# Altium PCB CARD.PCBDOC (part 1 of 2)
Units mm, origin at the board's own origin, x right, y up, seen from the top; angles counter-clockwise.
Board outline 129.79 x 109.73 mm, 2 copper layers (Top Layer, Bottom Layer); 204 components, 30 nets, 765 pads, 348 vias.
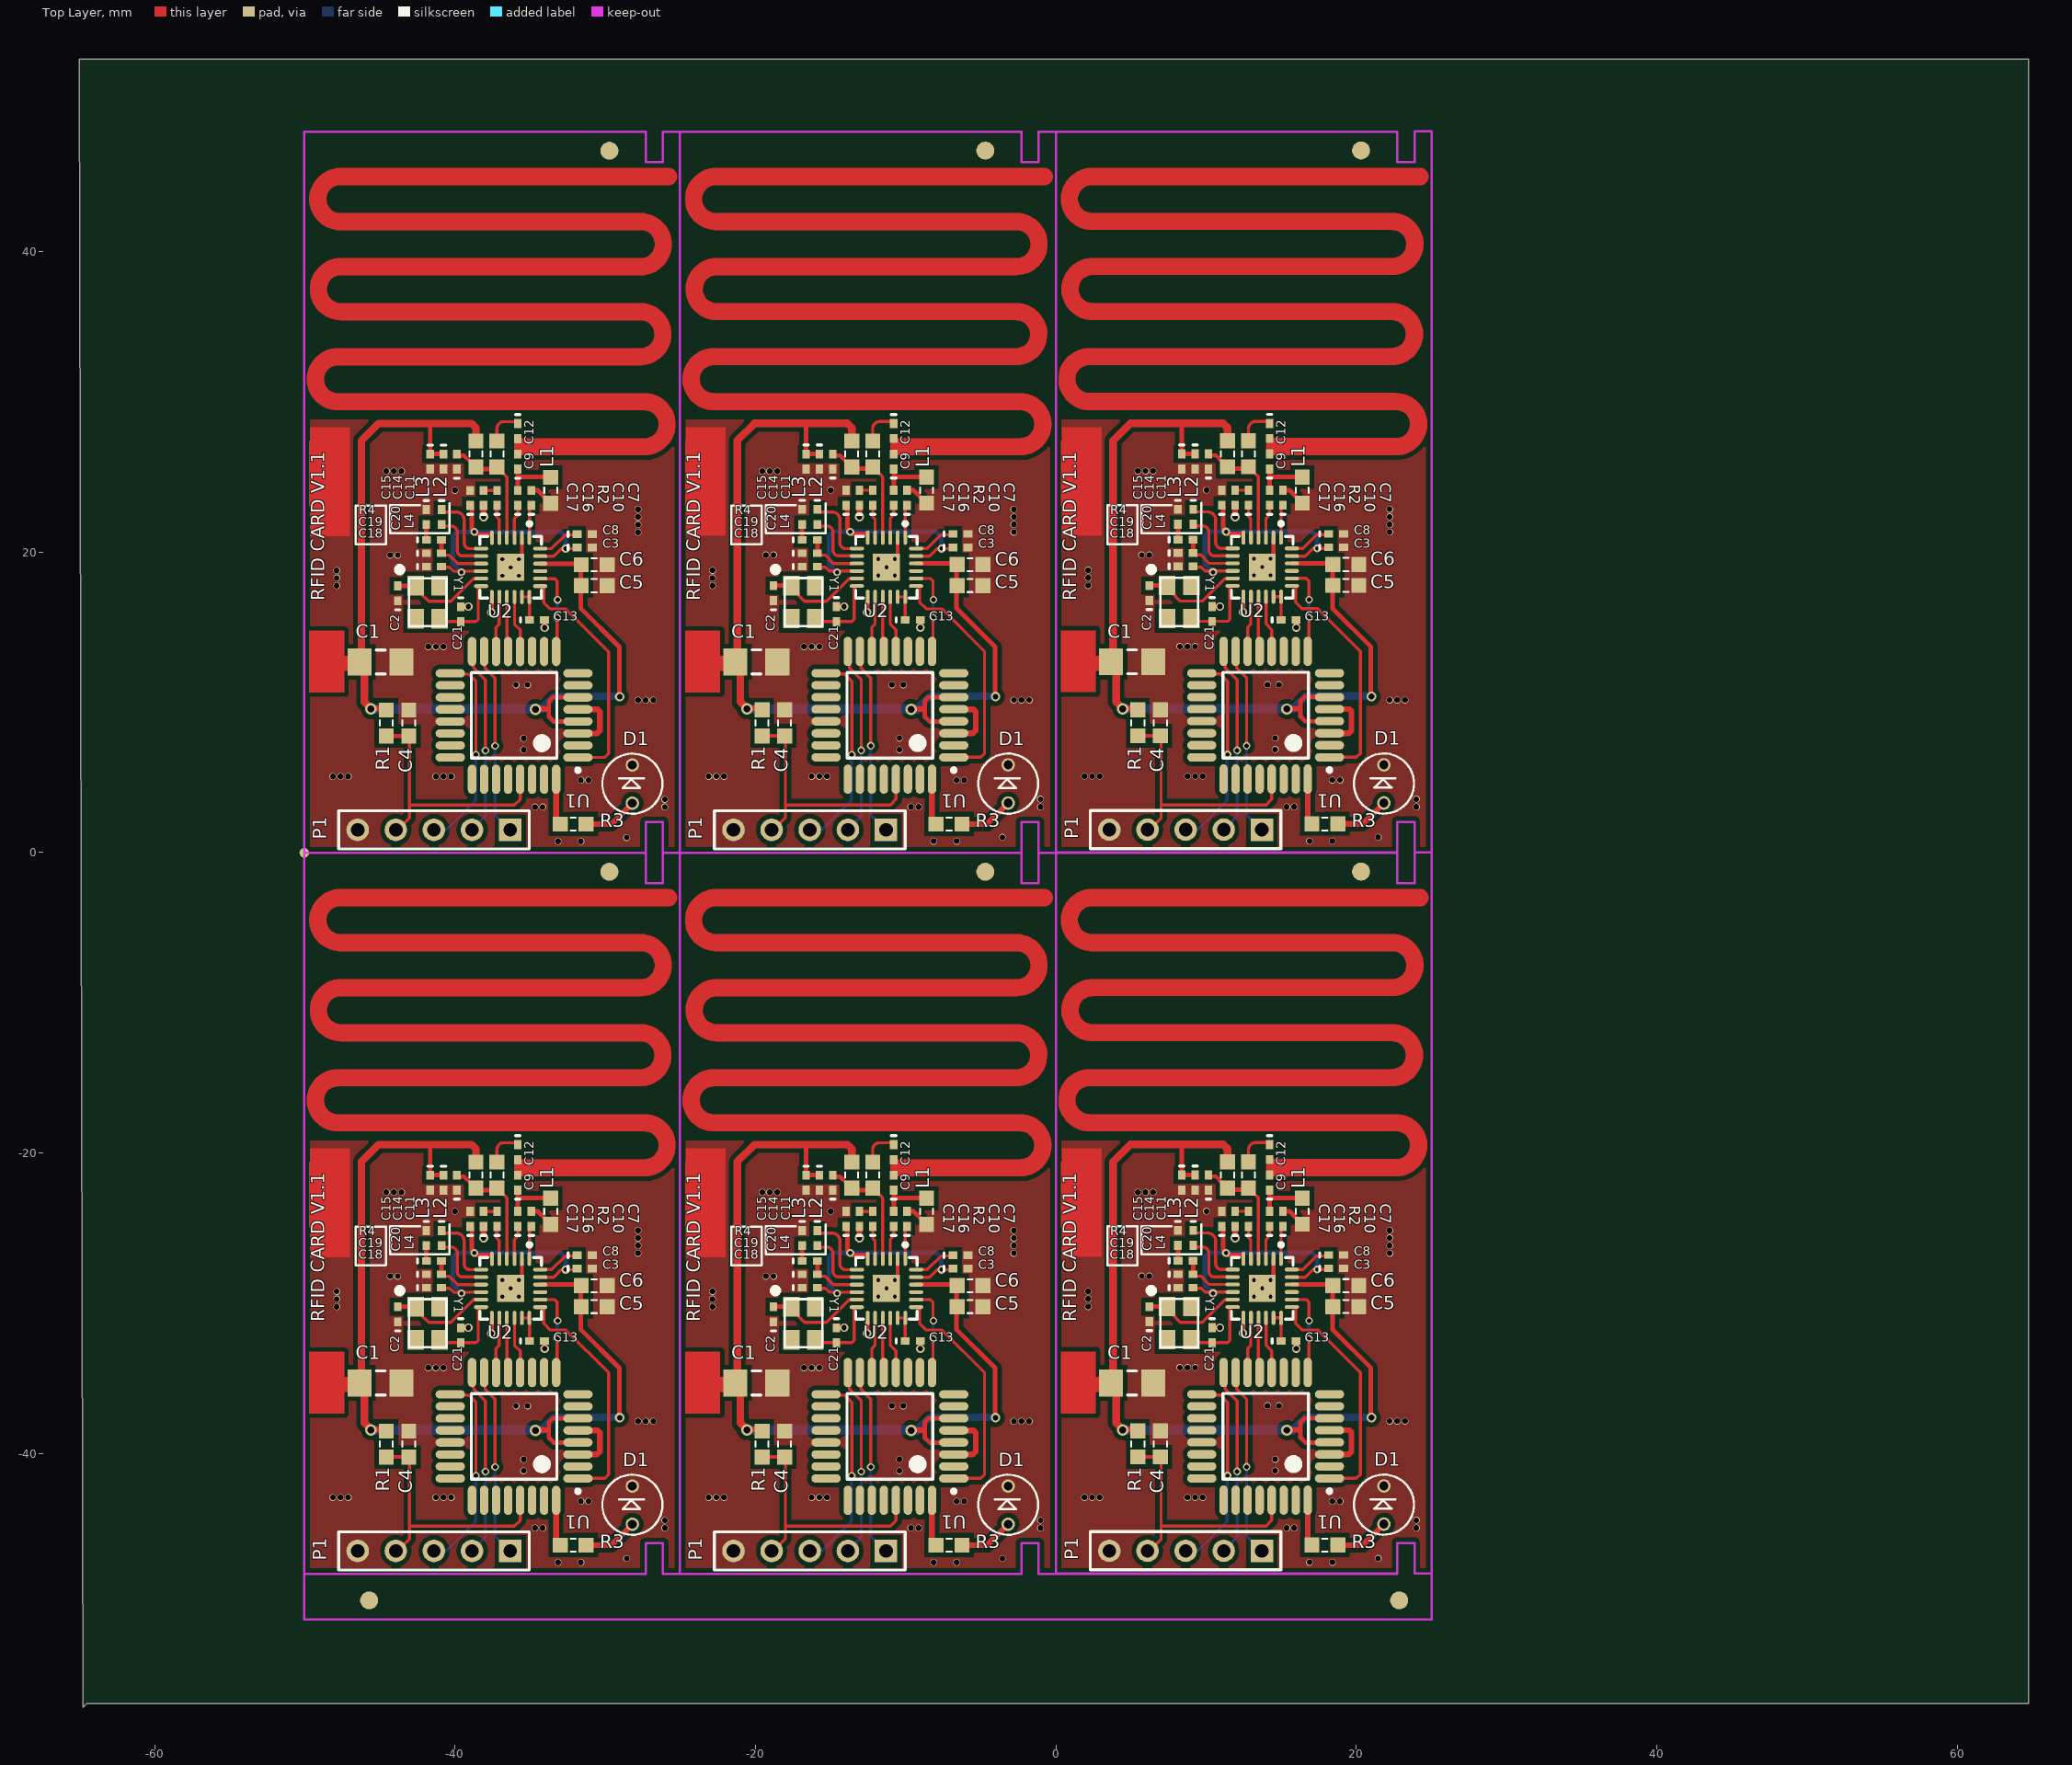
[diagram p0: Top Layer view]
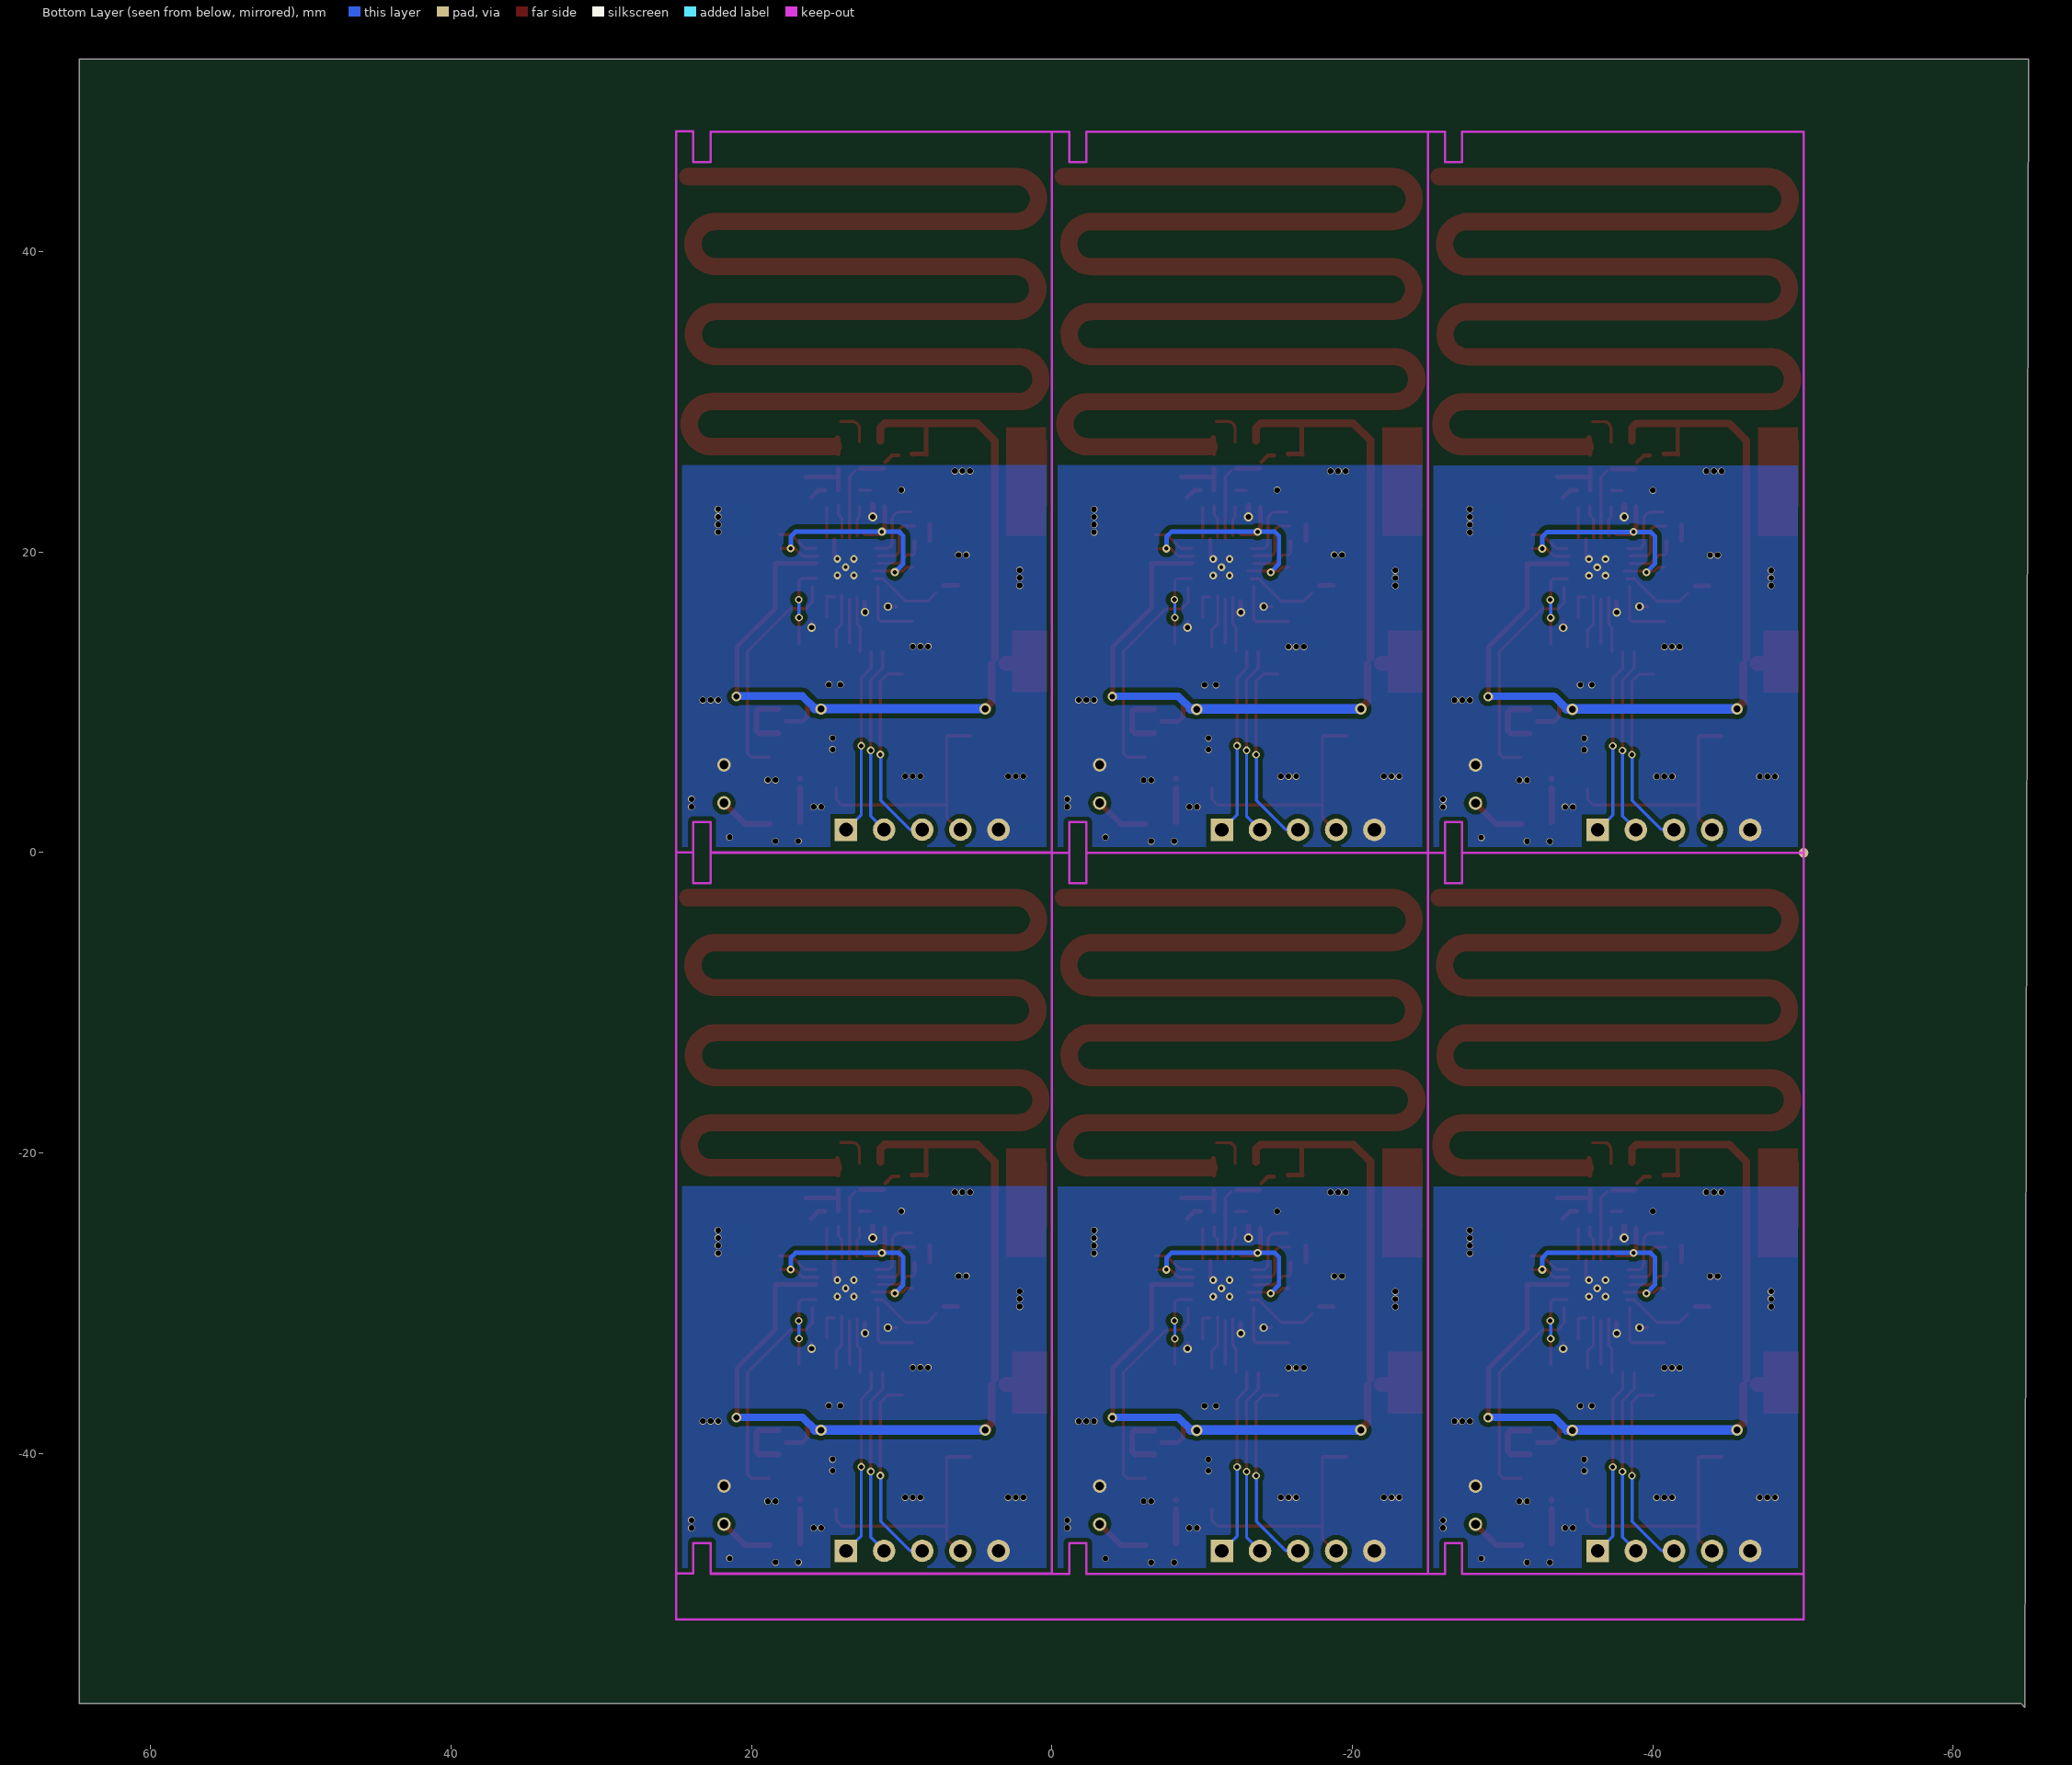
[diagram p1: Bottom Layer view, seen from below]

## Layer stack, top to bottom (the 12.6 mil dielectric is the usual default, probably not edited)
Top Layer: signal copper 0.0356
Dielectric: core 0.32, FR-4, Dk 4.8
Bottom Layer: signal copper 0.0356

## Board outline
-65.024,52.832 64.77,52.832 64.77,-56.642 -64.516,-56.642 -64.77,-56.896

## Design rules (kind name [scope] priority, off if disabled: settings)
Clearance [All] p1 off: gap=0.305
ComponentClearance [All] p1 off: gap=0.254 collisioncheckmode=3 verticalgap=0.254
HoleSize [All] p1: absolutevalues=TRUE maxlimit=2.54 minlimit=0 maxpercent=80.000 minpercent=20.000
PolygonConnect [All] p1: connectstyle=Direct reliefconductorwidth=0.254 reliefentries=4 polygonreliefangle="90 Angle"
RoutingVias [All] p1: holewidth=0.381 width=0.635 viastyle="Through Hole" minholewidth=0.203 minwidth=0.381 maxholewidth=2.032 maxwidth=1.27
SolderMaskExpansion [All] p1: expansion=0.102
TestPointUsage [All] p1: valid=0 allowmultiple=FALSE
Testpoint [All] p1: side=15 testpointundercomponent=TRUE minsize=1.016 maxsize=2.54 preferedsize=1.524 minholesize=0 maxholesize=1.016 preferedholesize=0.813 testpointgrid=0.025 style=1023 order=0123456789
Width [All] p1: maxlimit=2.54 minlimit=0.203 preferedwidth=0.254 minimp=50.000000 maximp=50.000000 favimp=50.000000
17 further rules are at their usual default settings.

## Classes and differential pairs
component class card: C1 C2 C3 C4 C5 C6 C7 C8 C9 C10 C11 C12 C13 C14 C15 C16 C17 C18 C19 C20 C21 D1 D2 L1 L2 L3 L4 P1 P3 R1 R2 R3 R4 U1 U2 Y1

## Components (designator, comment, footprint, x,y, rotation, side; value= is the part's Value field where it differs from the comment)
C1 "Cap" 3216[1206] -44.958,12.688 r180 top
C1 "Cap" 3216[1206] -44.958,-35.312 r180 top
C1 "Cap" 3216[1206] 5.08,-35.306 r180 top
C1 "Cap" 3216[1206] -19.939,-35.312 r180 top
C1 "Cap" 3216[1206] -19.939,12.694 r180 top
C1 "Cap" 3216[1206] 5.08,12.7 r180 top
C2 "Cap" 0402-A -43.815,17.26 r90 top
C2 "Cap" 0402-A -43.815,-30.74 r90 top
C2 "Cap" 0402-A 6.223,-30.734 r90 top
C2 "Cap" 0402-A -18.796,-30.74 r90 top
C2 "Cap" 0402-A -18.796,17.266 r90 top
C2 "Cap" 0402-A 6.223,17.272 r90 top
C3 "Cap" 0402-A -31.369,20.308 r0 top
C3 "Cap" 0402-A -31.369,-27.692 r0 top
C3 "Cap" 0402-A 18.669,-27.686 r0 top
C3 "Cap" 0402-A -6.35,-27.692 r0 top
C3 "Cap" 0402-A -6.35,20.314 r0 top
C3 "Cap" 0402-A 18.669,20.32 r0 top
C4 "Cap" 0603 -43.078,8.624 r90 top
C4 "Cap" 0603 -43.078,-39.376 r90 top
C4 "Cap" 0603 6.96,-39.37 r90 top
C4 "Cap" 0603 -18.059,-39.376 r90 top
C4 "Cap" 0603 -18.059,8.63 r90 top
C4 "Cap" 0603 6.96,8.636 r90 top
C5 "Cap" 0603 -30.734,17.768 r0 top
C5 "Cap" 0603 -30.734,-30.232 r0 top
C5 "Cap" 0603 19.304,-30.226 r0 top
C5 "Cap" 0603 -5.715,-30.232 r0 top
C5 "Cap" 0603 -5.715,17.774 r0 top
C5 "Cap" 0603 19.304,17.78 r0 top
C6 "Cap" 0603 -30.734,19.165 r0 top
C6 "Cap" 0603 -30.734,-28.835 r0 top
C6 "Cap" 0603 19.304,-28.829 r0 top
C6 "Cap" 0603 -5.715,-28.835 r0 top
C6 "Cap" 0603 -5.715,19.171 r0 top
C6 "Cap" 0603 19.304,19.177 r0 top
C7 "Cap" 0402-A -34.925,23.61 r90 top
C7 "Cap" 0402-A -34.925,-24.39 r90 top
C7 "Cap" 0402-A 15.113,-24.384 r90 top
C7 "Cap" 0402-A -9.906,-24.39 r90 top
C7 "Cap" 0402-A -9.906,23.616 r90 top
C7 "Cap" 0402-A 15.113,23.622 r90 top
C8 "Cap" 0402-A -31.369,21.197 r0 top
C8 "Cap" 0402-A -31.369,-26.803 r0 top
C8 "Cap" 0402-A 18.669,-26.797 r0 top
C8 "Cap" 0402-A -6.35,-26.803 r0 top
C8 "Cap" 0402-A -6.35,21.203 r0 top
C8 "Cap" 0402-A 18.669,21.209 r0 top
C9 "Cap" 0402-A -35.814,26.023 r90 top
C9 "Cap" 0402-A -35.814,-21.977 r90 top
C9 "Cap" 0402-A 14.224,-21.971 r90 top
C9 "Cap" 0402-A -10.795,-21.977 r90 top
C9 "Cap" 0402-A -10.795,26.029 r90 top
C9 "Cap" 0402-A 14.224,26.035 r90 top
C10 "Cap" 0402-A -35.814,23.61 r90 top
C10 "Cap" 0402-A -35.814,-24.39 r90 top
C10 "Cap" 0402-A 14.224,-24.384 r90 top
C10 "Cap" 0402-A -10.795,-24.39 r90 top
C10 "Cap" 0402-A -10.795,23.616 r90 top
C10 "Cap" 0402-A 14.224,23.622 r90 top
C11 "Cap" 0402-A -39.878,26.023 r90 top
C11 "Cap" 0402-A -39.878,-21.977 r90 top
C11 "Cap" 0402-A 10.16,-21.971 r90 top
C11 "Cap" 0402-A -14.859,-21.977 r90 top
C11 "Cap" 0402-A -14.859,26.029 r90 top
C11 "Cap" 0402-A 10.16,26.035 r90 top
C12 "Cap" 0402-A -35.814,28.055 r270 top
C12 "Cap" 0402-A -35.814,-19.945 r270 top
C12 "Cap" 0402-A 14.224,-19.939 r270 top
C12 "Cap" 0402-A -10.795,-19.945 r270 top
C12 "Cap" 0402-A -10.795,28.061 r270 top
C12 "Cap" 0402-A 14.224,28.067 r270 top
C13 "Cap" 0402-A -34.544,15.482 r0 top
C13 "Cap" 0402-A -34.544,-32.518 r0 top
C13 "Cap" 0402-A 15.494,-32.512 r0 top
C13 "Cap" 0402-A -9.525,-32.518 r0 top
C13 "Cap" 0402-A -9.525,15.488 r0 top
C13 "Cap" 0402-A 15.494,15.494 r0 top
C14 "Cap" 0402-A -40.767,26.023 r270 top
C14 "Cap" 0402-A -40.767,-21.977 r270 top
C14 "Cap" 0402-A 9.271,-21.971 r270 top
C14 "Cap" 0402-A -15.748,-21.977 r270 top
C14 "Cap" 0402-A -15.748,26.029 r270 top
C14 "Cap" 0402-A 9.271,26.035 r270 top
C15 "Cap" 0402-A -41.656,26.023 r270 top
C15 "Cap" 0402-A -41.656,-21.977 r270 top
C15 "Cap" 0402-A 8.382,-21.971 r270 top
C15 "Cap" 0402-A -16.637,-21.977 r270 top
C15 "Cap" 0402-A -16.637,26.029 r270 top
C15 "Cap" 0402-A 8.382,26.035 r270 top
C16 "Cap" 0402-A -38.1,23.61 r90 top
C16 "Cap" 0402-A -38.1,-24.39 r90 top
C16 "Cap" 0402-A 11.938,-24.384 r90 top
C16 "Cap" 0402-A -13.081,-24.39 r90 top
C16 "Cap" 0402-A -13.081,23.616 r90 top
C16 "Cap" 0402-A 11.938,23.622 r90 top
C17 "Cap" 0402-A -38.989,23.61 r90 top
C17 "Cap" 0402-A -38.989,-24.39 r90 top
C17 "Cap" 0402-A 11.049,-24.384 r90 top
C17 "Cap" 0402-A -13.97,-24.39 r90 top
C17 "Cap" 0402-A -13.97,23.616 r90 top
C17 "Cap" 0402-A 11.049,23.622 r90 top
C18 "Cap" 0402-A -41.402,19.038 r0 top
C18 "Cap" 0402-A -41.402,-28.962 r0 top
C18 "Cap" 0402-A 8.636,-28.956 r0 top
C18 "Cap" 0402-A -16.383,-28.962 r0 top
C18 "Cap" 0402-A -16.383,19.044 r0 top
C18 "Cap" 0402-A 8.636,19.05 r0 top
C19 "Cap" 0402-A -41.402,19.927 r0 top
C19 "Cap" 0402-A -41.402,-28.073 r0 top
C19 "Cap" 0402-A 8.636,-28.067 r0 top
C19 "Cap" 0402-A -16.383,-28.073 r0 top
C19 "Cap" 0402-A -16.383,19.933 r0 top
C19 "Cap" 0402-A 8.636,19.939 r0 top
C20 "Cap" 0402-A -41.91,22.34 r270 top
C20 "Cap" 0402-A -41.91,-25.66 r270 top
C20 "Cap" 0402-A 8.128,-25.654 r270 top
C20 "Cap" 0402-A -16.891,-25.66 r270 top
C20 "Cap" 0402-A -16.891,22.346 r270 top
C20 "Cap" 0402-A 8.128,22.352 r270 top
C21 "Cap" 0402-A -39.624,15.863 r270 top
C21 "Cap" 0402-A -39.624,-32.137 r270 top
C21 "Cap" 0402-A 10.414,-32.131 r270 top
C21 "Cap" 0402-A -14.605,-32.137 r270 top
C21 "Cap" 0402-A -14.605,15.869 r270 top
C21 "Cap" 0402-A 10.414,15.875 r270 top
D1 "LED0" LED-F3 -28.194,3.29 r90 top
D1 "LED0" LED-F3 -28.194,-44.71 r90 top
D1 "LED0" LED-F3 21.844,-44.704 r90 top
D1 "LED0" LED-F3 -3.175,-44.71 r90 top
D1 "LED0" LED-F3 -3.175,3.296 r90 top
D1 "LED0" LED-F3 21.844,3.302 r90 top
L1 "Inductor" 0603 -33.63,24.118 r270 top
L1 "Inductor" 0603 -33.63,-23.882 r270 top
L1 "Inductor" 0603 16.408,-23.876 r270 top
L1 "Inductor" 0603 -8.611,-23.882 r270 top
L1 "Inductor" 0603 -8.611,24.124 r270 top
L1 "Inductor" 0603 16.408,24.13 r270 top
L2 "Inductor" 0603 -37.211,26.531 r90 top
L2 "Inductor" 0603 -37.211,-21.469 r90 top
L2 "Inductor" 0603 12.827,-21.463 r90 top
L2 "Inductor" 0603 -12.192,-21.469 r90 top
L2 "Inductor" 0603 -12.192,26.537 r90 top
L2 "Inductor" 0603 12.827,26.543 r90 top
L3 "Inductor" 0603 -38.608,26.531 r90 top
L3 "Inductor" 0603 -38.608,-21.469 r90 top
L3 "Inductor" 0603 11.43,-21.463 r90 top
L3 "Inductor" 0603 -13.589,-21.469 r90 top
L3 "Inductor" 0603 -13.589,26.537 r90 top
L3 "Inductor" 0603 11.43,26.543 r90 top
L4 "Inductor" 0402-A -40.894,22.34 r270 top
L4 "Inductor" 0402-A -40.894,-25.66 r270 top
L4 "Inductor" 0402-A 9.144,-25.654 r270 top
L4 "Inductor" 0402-A -15.875,-25.66 r270 top
L4 "Inductor" 0402-A -15.875,22.346 r270 top
L4 "Inductor" 0402-A 9.144,22.352 r270 top
P1 "ISP" HDR1X5 -36.322,1.512 r180 top
P1 "ISP" HDR1X5 -36.322,-46.488 r180 top
P1 "ISP" HDR1X5 13.716,-46.482 r180 top
P1 "ISP" HDR1X5 -11.303,-46.488 r180 top
P1 "ISP" HDR1X5 -11.303,1.518 r180 top
P1 "ISP" HDR1X5 13.716,1.524 r180 top
R1 "Res1" 0603 -44.577,8.624 r90 top
R1 "Res1" 0603 -44.577,-39.376 r90 top
R1 "Res1" 0603 5.461,-39.37 r90 top
R1 "Res1" 0603 -19.558,-39.376 r90 top
R1 "Res1" 0603 -19.558,8.63 r90 top
R1 "Res1" 0603 5.461,8.636 r90 top
R2 "Res1" 0402-A -37.211,23.61 r90 top
R2 "Res1" 0402-A -37.211,-24.39 r90 top
R2 "Res1" 0402-A 12.827,-24.384 r90 top
R2 "Res1" 0402-A -12.192,-24.39 r90 top
R2 "Res1" 0402-A -12.192,23.616 r90 top
R2 "Res1" 0402-A 12.827,23.622 r90 top
R3 "Res1" 0603 -32.131,1.893 r0 top
R3 "Res1" 0603 -32.131,-46.107 r0 top
R3 "Res1" 0603 17.907,-46.101 r0 top
R3 "Res1" 0603 -7.112,-46.107 r0 top
R3 "Res1" 0603 -7.112,1.899 r0 top
R3 "Res1" 0603 17.907,1.905 r0 top
R4 "Res1" 0402-A -41.402,20.816 r0 top
R4 "Res1" 0402-A -41.402,-27.184 r0 top
R4 "Res1" 0402-A 8.636,-27.178 r0 top
R4 "Res1" 0402-A -16.383,-27.184 r0 top
R4 "Res1" 0402-A -16.383,20.822 r0 top
R4 "Res1" 0402-A 8.636,20.828 r0 top
U1 "ATmega8-16AC" 32A_M -36.068,9.132 r180 top
U1 "ATmega8-16AC" 32A_M -36.068,-38.868 r180 top
U1 "ATmega8-16AC" 32A_M 13.97,-38.862 r180 top
U1 "ATmega8-16AC" 32A_M -11.049,-38.868 r180 top
U1 "ATmega8-16AC" 32A_M -11.049,9.138 r180 top
U1 "ATmega8-16AC" 32A_M 13.97,9.144 r180 top
U2 "A7139" QFN24N -36.297,18.987 r270 top
U2 "A7139" QFN24N -36.297,-29.013 r270 top
U2 "A7139" QFN24N 13.741,-29.007 r270 top
U2 "A7139" QFN24N -11.278,-29.013 r270 top
U2 "A7139" QFN24N -11.278,18.993 r270 top
U2 "A7139" QFN24N 13.741,18.999 r270 top
Y1 "12.8M CL=20pF" XT3225 -41.021,17.768 r270 top
Y1 "12.8M CL=20pF" XT3225 -41.021,-30.232 r270 top
Y1 "12.8M CL=20pF" XT3225 9.017,-30.226 r270 top
Y1 "12.8M CL=20pF" XT3225 -16.002,-30.232 r270 top
Y1 "12.8M CL=20pF" XT3225 -16.002,17.774 r270 top
Y1 "12.8M CL=20pF" XT3225 9.017,17.78 r270 top

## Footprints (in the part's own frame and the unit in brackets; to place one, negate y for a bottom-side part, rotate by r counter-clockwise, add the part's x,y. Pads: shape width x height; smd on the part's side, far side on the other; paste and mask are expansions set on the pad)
32A_M [mm] "32-Pin Thin Quad Flat Pack 0.8 mm Pitch, IPC Low Density"
  oval 1.95x0.559 smd: 1(-4.25,2.8) 2(-4.25,2) 3(-4.25,1.2) 4(-4.25,0.4) 5(-4.25,-0.4) 6(-4.25,-1.2) 7(-4.25,-2) 8(-4.25,-2.8) 17(4.25,-2.8) 18(4.25,-2) 19(4.25,-1.2) 20(4.25,-0.4) 21(4.25,0.4) 22(4.25,1.2) 23(4.25,2) 24(4.25,2.8)
  oval 0.559x1.95 smd: 9(-2.8,-4.25) 10(-2,-4.25) 11(-1.2,-4.25) 12(-0.4,-4.25) 13(0.4,-4.25) 14(1.2,-4.25) 15(2,-4.25) 16(2.8,-4.25) 25(2.8,4.25) 26(2,4.25) 27(1.2,4.25) 28(0.4,4.25) 29(-0.4,4.25) 30(-1.2,4.25) 31(-2,4.25) 32(-2.8,4.25)
  silkscreen extent -4.38,-2.85 2.85,3.77, body extent -3.5,-3.5 3.5,3.5, height 1.2
0402-A [mm] "Chip Inductor; Body 1 x 0.5 mm (LxW typ)"
  rect 0.6x0.5 smd: 1(-0.5,0) 2(0.5,0)
  silkscreen extent -1.1,-0.15 -1.1,0.15
0603 [mm]
  rect 1x1 smd: 1(-0.864,0) 2(0.864,0)
  silkscreen extent -0.18,-0.43 0.18,0.43
3216[1206] [mm] "Chip Resistor; Body 3.2 x 1.6 mm (LxW typ)"
  rect 1.6x1.8 smd: 1(-1.4,0) 2(1.4,0)
  silkscreen extent -0.3,-0.8 0.3,0.8
HDR1X5 [mm] "Connector; Header; 5 Position"
  rect 1.5x1.5 hole 0.9: 1(0,0)
  round 1.5 hole 0.9: 2(2.54,0) 3(5.08,0) 4(7.62,0) 5(10.16,0)
  silkscreen extent -1.27,-1.27 11.43,1.27
LED-F3 [mm]
  round 0.9 hole 0.6: 1(0,0) 2(2.54,0)
  silkscreen extent -0.71,-2 3.29,2
QFN24N [mm] "QFN, 24-Leads, Body 4.1x4.1mm (max), Pitch 0.50mm, IPC Medium Density"
  oval 0.95x0.25 smd: 1(-1.97,1.25) 2(-1.97,0.75) 3(-1.97,0.25) 4(-1.97,-0.25) 5(-1.97,-0.75) 6(-1.97,-1.25) 13(1.97,-1.25) 14(1.97,-0.75) 15(1.97,-0.25) 16(1.97,0.25) 17(1.97,0.75) 18(1.97,1.25)
  oval 0.25x0.95 smd: 7(-1.25,-1.97) 8(-0.75,-1.97) 9(-0.25,-1.97) 10(0.25,-1.97) 11(0.75,-1.97) 12(1.25,-1.97) 19(1.25,1.97) 20(0.75,1.97) 21(0.25,1.97) 22(-0.25,1.97) 23(-0.75,1.97) 24(-1.25,1.97)
  rect 1.8x1.8 smd: 25(0,0)
  silkscreen extent -3.02,-2.05 2.05,2.05, body extent -2.05,-2.05 2.05,2.05, height 0.8
XT3225 [mm]
  rect 1.3x1.1 smd: 1(0,-1.6) 2(2.2,-1.6) 3(2.2,0) 4(0,0)
  silkscreen extent -1.25,-2.85 2.7,0.45

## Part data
C1 C1 C1 C1 C1 C1 C2 C2 C2 C2 C2 C2 C3 C3 C3 C3 C3 C3 C4 C4 C4 C4 C4 C4 C5 C5 C5 C5 C5 C5 C6 C6 C6 C6 C6 C6 C7 C7 C7 C7 C7 C7 C8 C8 C8 C8 C8 C8 C9 C9 C9 C9 C9 C9 C10 C10 C10 C10 C10 C10 C11 C11 C11 C11 C11 C11 C12 C12 C12 C12 C12 C12 C13 C13 C13 C13 C13 C13 C14 C14 C14 C14 C14 C14 C15 C15 C15 C15 C15 C15 C16 C16 C16 C16 C16 C16 C17 C17 C17 C17 C17 C17 C18 C18 C18 C18 C18 C18 C19 C19 C19 C19 C19 C19 C20 C20 C20 C20 C20 C20 C21 C21 C21 C21 C21 C21: "Capacitor"
D1 D1 D1 D1 D1 D1: "Typical INFRARED GaAs LED"
P1 P1 P1 P1 P1 P1: library part "Header 5", "Header, 5-Pin"
R1 R1 R1 R1 R1 R1 R2 R2 R2 R2 R2 R2 R3 R3 R3 R3 R3 R3 R4 R4 R4 R4 R4 R4: "Resistor"
U1 U1 U1 U1 U1 U1: "8-Bit AVR Microcontroller with 8K Bytes of In-System Programmable Flash Memory"
Y1 Y1 Y1 Y1 Y1 Y1: library part XTAL, "Crystal Oscillator"

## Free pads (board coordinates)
  round 1.2 smd: 3(-29.718,-1.276) 3(-29.718,46.724) 3(-4.699,-1.276) 3(-4.699,46.73) 3(20.32,-1.27) 3(20.32,46.736) 6(22.86,-49.784) 7(-45.72,-49.784)
  round 0.635 all layers, no hole: 4(-50.038,-0.018)

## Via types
v1: diameter 0.457, hole 0.381, Top Layer to Bottom Layer, 228 vias
v2: diameter 0.508, hole 0.305, Top Layer to Bottom Layer, 30 vias
v3: diameter 0.508, hole 0.254, Top Layer to Bottom Layer, tented top, 30 vias
v4: diameter 0.559, hole 0.356, Top Layer to Bottom Layer, 18 vias
v5: diameter 0.533, hole 0.279, Top Layer to Bottom Layer, 18 vias
v6: diameter 0.762, hole 0.457, Top Layer to Bottom Layer, 12 vias
v7: diameter 0.61, hole 0.356, Top Layer to Bottom Layer, 6 vias
v8: diameter 0.635, hole 0.381, Top Layer to Bottom Layer, 6 vias

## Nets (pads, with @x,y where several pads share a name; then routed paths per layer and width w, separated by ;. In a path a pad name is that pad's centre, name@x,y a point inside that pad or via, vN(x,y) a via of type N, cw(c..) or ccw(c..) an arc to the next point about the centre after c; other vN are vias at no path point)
GIO1: U1.1@18.22,6.344 U2.19@15.711,17.749 | length 15.1
  Top Layer w0.203: U2.19@15.951,17.704 15.951,16.662 16.383,16.231 17.424,16.231 20.269,13.386 20.269,6.604 20.015,6.35 U1.1@18.821,6.35
GIO2: U1.9@16.77,13.394 U2.20@15.711,18.249 | length 5.4
  Top Layer w0.203: U2.20@15.711,18.249 16.676,18.249 16.84,18.085 v2@16.84,16.815 ; U1.9@16.84,13.9 v2(16.84,15.646)
  Bottom Layer w0.203: v2@16.84,15.723 v2@16.84,16.942
  other v2: 16.866,16.84
GND: C1.1@6.48,12.7 C2.1@6.223,16.772 C3.2@19.169,20.32 C4.2@6.96,9.5 C5.2@20.168,17.78 C6.2@20.168,19.177 C7.2@15.113,24.122 C8.2@19.169,21.209 C11.1@10.16,25.535 C13.2@15.994,15.494 C14.2@9.271,25.535 C15.2@8.382,25.535 C16.1@11.938,23.122 C17.2@11.049,24.122 C18.1@8.136,19.05 C19.1@8.136,19.939 C20.1@8.128,22.852 C21.1@10.414,16.375 D1.2@21.844,5.842 L1.2@16.408,23.266 P1.5@3.556,1.524 U1.3@18.22,7.944 U1.5@18.22,9.544 U1.21@9.72,8.744 U2.2@14.491,20.969 U2.13@12.491,17.029 U2.25@13.741,18.999 | length 8.5
  Top Layer w0.254: C21.1@10.643,16.358 v4@10.871,16.358 ; U2.25@14.491,19.749 U2.2@14.491,20.853 ; v4@16.002,15.008 C13.2@16.002,15.367
  Top Layer w0.305: v4@12.471,16.027 U2.13@12.471,16.722 ; C7.2@15.113,24.122 15.553,24.122 L1.2@16.027,23.647
  Top Layer w0.381: v7@11.938,22.454 C16.1@11.938,23.122 ; U1.3@18.22,7.944 19.501,7.944 19.685,8.128 19.685,9.398 19.539,9.544 U1.5@18.22,9.544
  other v1: 16.891,0.762 18.415,0.762 21.463,1.016 15.367,3.048 15.875,3.048 24.003,3.048 24.003,3.556 18.415,4.826 18.923,4.826 1.905,5.08 2.413,5.08 2.921,5.08 8.763,5.08 9.271,5.08 9.779,5.08 14.605,6.858 14.605,7.62 22.225,10.16 22.733,10.16 23.241,10.16 14.097,11.176 14.859,11.176 8.255,13.716 8.763,13.716 9.271,13.716 2.159,17.78 2.159,18.288 2.159,18.796 5.715,19.812 6.223,19.812 22.225,21.336 22.225,21.844 22.225,22.352 22.225,22.86 10.033,24.13 5.461,25.4 5.969,25.4 6.477,25.4
  other v3: 13.191,18.449 14.291,18.449 13.741,18.999 13.191,19.549 14.291,19.549
  other v4: 16.002,14.986 12.446,16.002 10.922,16.383
  other v7: 11.938,22.352
MISO: P1.2@11.176,1.524 U1.16@11.17,13.394 | length 12.6
  Top Layer w0.203: U1.16@11.278,13.386 11.278,12.294 12.065,11.506 v2@12.065,6.858
  Bottom Layer w0.203: P1.2@11.176,1.397 11.176,1.549 12.065,2.438 v2(12.065,6.807)
MOSI: P1.1@13.716,1.524 U1.15@11.97,13.394 | length 12.6
  Top Layer w0.203: U1.15@12.04,13.411 12.04,12.294 12.7,11.633 v2(12.7,7.112)
  Bottom Layer w0.203: v2(12.7,7.112) 12.7,2.515 13.64,1.575 P1.1@13.64,1.473
MSCK: P1.3@8.636,1.524 U1.17@9.72,11.944 | length 13
  Top Layer w0.203: U1.17@9.957,11.887 10.947,11.887 11.43,11.405 v2(11.43,6.528)
  Bottom Layer w0.203: P1.3@8.788,1.549 9.474,1.549 11.405,3.48 v2@11.405,6.528
NetC2_2: C2.2@6.223,17.772 U2.11@11.771,18.249 Y1.1@7.417,17.78 | length 5.9
  Top Layer w0.203: Y1.1@7.722,17.297 8.28,16.739 9.754,16.739 11.252,18.237 U2.11@11.786,18.237
  Top Layer w0.305: C2.2@6.274,17.78 Y1.1@7.231,17.78
NetC7_1: C7.1@15.113,23.122 U2.1@14.991,20.969 | length 2
  Top Layer w0.203: U2.1@14.991,20.969 C7.1@14.991,23
NetC8_1: C8.1@18.169,21.209 U2.24@15.711,20.249 | length 2.8
  Top Layer w0.203: U2.24@15.711,20.249 16.465,20.249 17.374,21.158 C8.1@18.136,21.158
NetC9_1: C9.1@14.224,25.535 C10.2@14.224,24.122 L1.1@16.408,24.994 | length 3.6
  Top Layer w0.305: C10.2@14.224,24.122 C9.1@14.224,25.552 ; 14.275,25.019 L1.1@16.408,25.019
NetC9_2: C9.2@14.224,26.535 C12.2@14.224,27.567 | length 160
  Top Layer w0.203: C12.2@14.199,27.483 14.224,27.488 C12.2@14.24,27.491
  Top Layer w0.33: C9.2@14.24,26.544 C12.2@14.24,27.491 ; C12.2@14.282,27.559 C12.2@14.292,27.635
  Top Layer w1.15: 2.388,42.01 22.339,42.01 cw(c22.402,40.512) 22.326,39.014 2.515,39.014 ccw(c2.439,37.515) 2.502,36.017 22.314,36.017 cw(c22.377,34.518) 22.301,33.02 ; 2.388,45.007 24.257,45.007 ; 2.464,42.012 cw(c2.401,43.51) 2.476,45.008 ; 14.557,27.026 22.581,27.026 ccw(c22.656,28.524) 22.593,30.022 2.299,30.022 cw(c2.236,31.522) 2.311,33.02 22.341,33.02
NetC10_1: C10.1@14.224,23.122 U2.3@13.991,20.969 | length 2.2
  Top Layer w0.203: U2.3@13.991,20.969 13.991,22.246 14.224,22.479 C10.1@14.224,23.122
NetC11_2: C11.2@10.16,26.535 L2.1@12.827,25.679 L3.1@11.43,25.679 U2.4@13.491,20.969 | length 7.2
  Top Layer w0.203: L2.1@13.081,25.425 13.487,25.019 U2.4@13.487,21.057 ; U2.4@13.487,20.904 13.488,20.969 U2.4@13.487,20.93
  Top Layer w0.254: C11.2@10.236,26.441 10.643,26.441 L3.1@11.092,25.992
  Top Layer w0.305: L3.1@11.201,25.552 L2.1@12.751,25.552
NetC12_1: C12.1@14.224,28.567 L2.2@12.827,27.407 | length 2.4
  Top Layer w0.203: L2.2@12.827,27.33 12.827,28.243 cw(c13.261,28.243) 12.954,28.55 ; 12.979,28.575 cw(c13.271,28.283) 13.271,28.696 C12.1@14.065,28.696
NetC13_1: C13.1@14.994,15.494 U2.17@14.491,17.029 U2.18@14.991,17.029 | length 1.9
  Top Layer w0.203: U2.17@14.491,17.029 U2.18@14.991,17.029 C13.1@14.991,15.674
NetC16_2: C16.2@11.938,24.122 R2.2@12.827,24.122 | length 0.7
  Top Layer w0.203: C16.2@12.073,24.122 R2.2@12.802,24.122
NetC19_2: C19.2@9.136,19.939 R4.2@9.136,20.828 U2.9@11.771,19.249 | length 3.3
  Top Layer w0.203: C19.2@9.144,19.939 9.271,19.812 9.652,19.812 10.211,19.253 U2.9@11.582,19.253
  Top Layer w0.305: C19.2@9.144,20.134 R4.2@9.144,20.701
NetC20_2: C20.2@8.128,21.852 R4.1@8.136,20.828 | length 1.1
  Top Layer w0.305: R4.1@8.128,20.752 C20.2@8.128,21.844
NetC21_2: C21.2@10.414,15.375 U2.12@11.771,17.749 Y1.3@9.017,15.58 | length 4.6
  Top Layer w0.203: Y1.3@9.271,15.392 11.43,15.392 11.582,15.545 U2.12@11.582,17.749
NetD1_1: D1.1@21.844,3.302 R3.2@18.771,1.905 | length 3.6
  Top Layer w0.381: R3.2@18.796,1.905 20.447,1.905 D1.1@21.844,3.302
NetL4_1: L4.1@9.144,22.852 U2.7@11.771,20.249 | length 4.5
  Top Layer w0.203: L4.1@9.347,22.682 10.135,22.682 ; 10.109,22.682 cw(c10.109,22.149) 10.643,22.149 ; 10.643,22.174 10.643,20.625 ccw(c11.024,20.625) 11.024,20.244 U2.7@11.735,20.244
NetL4_2: L4.2@9.144,21.852 U2.8@11.771,19.749 | length 4.1
  Top Layer w0.203: L4.2@9.169,21.742 9.779,21.742 cw(c9.779,21.336) 10.185,21.336 10.185,20.117 ccw(c10.541,20.117) 10.541,19.761 ; 10.516,19.761 U2.8@11.582,19.761
NetR2_1: R2.1@12.827,23.122 U2.5@12.991,20.969 | length 2
  Top Layer w0.203: R2.1@12.827,23.038 12.827,22.352 12.979,22.2 U2.5@12.979,21.107
NetR3_1: R3.1@17.043,1.905 U1.32@16.77,4.894 | length 2.3
  Top Layer w0.381: R3.1@16.764,2.032 U1.32@16.764,4.318 ; U1.32@16.764,4.894 U1.32@16.764,4.953
RST: C4.1@6.96,7.772 P1.4@6.096,1.524 R1.1@5.461,7.772 U1.29@14.37,4.894 | length 16.4
  Top Layer w0.203: P1.4@6.096,1.397 7.01,2.311 C4.1@7.01,7.772 ; 7.061,3.175 13.995,3.175 14.376,3.556 U1.29@14.376,4.267
  Top Layer w0.254: R1.1@5.461,7.772 C4.1@6.96,7.772
SCK: U1.13@13.57,13.394 U2.15@13.491,17.029 | length 2.9
  Top Layer w0.203: U1.13@13.487,13.945 U2.15@13.487,16.866
SCS: U1.14@12.77,13.394 U2.14@12.991,17.029 | length 3.7
  Top Layer w0.203: U1.14@12.77,13.394 12.77,15.005 12.979,15.215 U2.14@12.979,16.993
SDIO: U1.12@14.37,13.394 U2.16@13.991,17.029 | length 3.6
  Top Layer w0.203: U2.16@13.995,17.029 U2.16@13.995,17.043 ; U2.16@13.995,17.12 13.995,15.215 14.376,14.834 U1.12@14.376,13.691
VCC: C1.2@3.68,12.7 C5.1@18.44,17.78 C6.1@18.44,19.177 C14.1@9.271,26.535 C15.1@8.382,26.535 L3.2@11.43,27.407 R1.2@5.461,9.5 U1.4@18.22,8.744 U1.6@18.22,10.344 U2.22@15.711,19.249 | length 66.3
  Top Layer w0.305: C15.1@8.357,26.518 8.382,26.543 8.382,28.575 ; C15.1@8.357,26.543 C14.1@9.322,26.543 ; U2.22@15.711,19.249 C6.1@18.44,19.249 ; U1.4@17.729,8.738 16.612,8.738 16.281,9.068 16.281,10.084 16.561,10.363 U1.6@17.755,10.363 ; C6.1@18.415,19.177 18.415,16.256 20.98,13.691 v8@20.98,10.414
  Top Layer w0.381: v6@15.418,9.576 16.205,9.576
  Top Layer w0.406: v6@4.445,9.601 R1.2@5.359,9.601
  Top Layer w0.508: C1.2@3.81,12.954 3.81,27.432 4.953,28.575 11.151,28.575 11.43,28.296 L3.2@11.43,27.407 ; C1.2@4.013,12.548 4.013,10.033 v6@4.445,9.601
  Top Layer w1.016: 1.854,12.598 C1.2@3.073,12.598
  Bottom Layer w0.508: 15.773,9.576 16.612,10.414 v8@21.006,10.414
  Bottom Layer w0.635: v6@4.47,9.576 15.773,9.576
  other v6: 15.392,9.55 4.445,9.576
  other v8: 21.006,10.389
VDA: C3.1@18.169,20.32 C17.1@11.049,23.122 C18.2@9.136,19.05 U2.6@12.491,20.969 U2.10@11.771,18.749 U2.23@15.711,19.749 | length 19.5
  Top Layer w0.203: C18.2@9.296,18.999 9.677,18.999 9.931,18.745 U2.10@11.963,18.745 ; U2.23@15.596,19.736 16.612,19.736 17.12,20.244 C3.1@18.034,20.244
  Top Layer w0.305: C17.1@11.151,23.02 11.151,21.539 11.481,21.209 U2.6@12.446,21.209
  Bottom Layer w0.305: v5(10.465,18.669) 9.906,19.228 9.906,21.082 10.185,21.361 17.069,21.361 17.399,21.031 v5(17.399,20.244)
  other v5: 11.328,21.361
pads on no net: C1.1@6.48,-35.306 C1.1@-18.539,12.694 C1.1@-18.539,-35.312 C1.1@-43.558,12.688 C1.1@-43.558,-35.312 C1.2@3.68,-35.306 C1.2@-21.339,12.694 C1.2@-21.339,-35.312 C1.2@-46.358,12.688 C1.2@-46.358,-35.312 C2.1@6.223,-31.234 C2.1@-18.796,16.766 C2.1@-18.796,-31.24 C2.1@-43.815,16.76 C2.1@-43.815,-31.24 C2.2@6.223,-30.234 C2.2@-18.796,17.766 C2.2@-18.796,-30.24 C2.2@-43.815,17.76 C2.2@-43.815,-30.24 C3.1@18.169,-27.686 C3.1@-6.85,20.314 C3.1@-6.85,-27.692 C3.1@-31.869,20.308 C3.1@-31.869,-27.692 C3.2@19.169,-27.686 C3.2@-5.85,20.314 C3.2@-5.85,-27.692 C3.2@-30.869,20.308 C3.2@-30.869,-27.692 C4.1@6.96,-40.234 C4.1@-18.059,7.766 C4.1@-18.059,-40.24 C4.1@-43.078,7.76 C4.1@-43.078,-40.24 C4.2@6.96,-38.506 C4.2@-18.059,9.494 C4.2@-18.059,-38.512 C4.2@-43.078,9.488 C4.2@-43.078,-38.512 C5.1@18.44,-30.226 C5.1@-6.579,17.774 C5.1@-6.579,-30.232 C5.1@-31.598,17.768 C5.1@-31.598,-30.232 C5.2@20.168,-30.226 C5.2@-4.851,17.774 C5.2@-4.851,-30.232 C5.2@-29.87,17.768 C5.2@-29.87,-30.232 C6.1@18.44,-28.829 C6.1@-6.579,19.171 C6.1@-6.579,-28.835 C6.1@-31.598,19.165 C6.1@-31.598,-28.835 C6.2@20.168,-28.829 C6.2@-4.851,19.171 C6.2@-4.851,-28.835 C6.2@-29.87,19.165 C6.2@-29.87,-28.835 C7.1@15.113,-24.884 C7.1@-9.906,23.116 C7.1@-9.906,-24.89 C7.1@-34.925,23.11 C7.1@-34.925,-24.89 C7.2@15.113,-23.884 C7.2@-9.906,24.116 C7.2@-9.906,-23.89 C7.2@-34.925,24.11 C7.2@-34.925,-23.89 C8.1@18.169,-26.797 C8.1@-6.85,21.203 C8.1@-6.85,-26.803 C8.1@-31.869,21.197 C8.1@-31.869,-26.803 C8.2@19.169,-26.797 C8.2@-5.85,21.203 C8.2@-5.85,-26.803 C8.2@-30.869,21.197 C8.2@-30.869,-26.803 C9.1@14.224,-22.471 C9.1@-10.795,25.529 C9.1@-10.795,-22.477 C9.1@-35.814,25.523 C9.1@-35.814,-22.477 C9.2@14.224,-21.471 C9.2@-10.795,26.529 C9.2@-10.795,-21.477 C9.2@-35.814,26.523 C9.2@-35.814,-21.477 C10.1@14.224,-24.884 C10.1@-10.795,23.116 C10.1@-10.795,-24.89 C10.1@-35.814,23.11 C10.1@-35.814,-24.89 C10.2@14.224,-23.884 C10.2@-10.795,24.116 C10.2@-10.795,-23.89 C10.2@-35.814,24.11 C10.2@-35.814,-23.89 C11.1@10.16,-22.471 C11.1@-14.859,25.529 C11.1@-14.859,-22.477 C11.1@-39.878,25.523 C11.1@-39.878,-22.477 C11.2@10.16,-21.471 C11.2@-14.859,26.529 C11.2@-14.859,-21.477 C11.2@-39.878,26.523 C11.2@-39.878,-21.477 C12.1@14.224,-19.439 C12.1@-10.795,28.561 C12.1@-10.795,-19.445 C12.1@-35.814,28.555 C12.1@-35.814,-19.445 C12.2@14.224,-20.439 C12.2@-10.795,27.561 C12.2@-10.795,-20.445 C12.2@-35.814,27.555 C12.2@-35.814,-20.445 C13.1@14.994,-32.512 C13.1@-10.025,15.488 C13.1@-10.025,-32.518 C13.1@-35.044,15.482 C13.1@-35.044,-32.518 C13.2@15.994,-32.512 C13.2@-9.025,15.488 C13.2@-9.025,-32.518 C13.2@-34.044,15.482 C13.2@-34.044,-32.518 C14.1@9.271,-21.471 C14.1@-15.748,26.529 C14.1@-15.748,-21.477 C14.1@-40.767,26.523 C14.1@-40.767,-21.477 C14.2@9.271,-22.471 C14.2@-15.748,25.529 C14.2@-15.748,-22.477 C14.2@-40.767,25.523 C14.2@-40.767,-22.477 C15.1@8.382,-21.471 C15.1@-16.637,26.529 C15.1@-16.637,-21.477 C15.1@-41.656,26.523 C15.1@-41.656,-21.477 C15.2@8.382,-22.471 C15.2@-16.637,25.529 C15.2@-16.637,-22.477 C15.2@-41.656,25.523 C15.2@-41.656,-22.477 C16.1@11.938,-24.884 C16.1@-13.081,23.116 C16.1@-13.081,-24.89 C16.1@-38.1,23.11 C16.1@-38.1,-24.89 C16.2@11.938,-23.884 C16.2@-13.081,24.116 C16.2@-13.081,-23.89 C16.2@-38.1,24.11 C16.2@-38.1,-23.89 C17.1@11.049,-24.884 C17.1@-13.97,23.116 C17.1@-13.97,-24.89 C17.1@-38.989,23.11 C17.1@-38.989,-24.89 C17.2@11.049,-23.884 C17.2@-13.97,24.116 C17.2@-13.97,-23.89 C17.2@-38.989,24.11 C17.2@-38.989,-23.89 C18.1@8.136,-28.956 C18.1@-16.883,19.044 C18.1@-16.883,-28.962 C18.1@-41.902,19.038 C18.1@-41.902,-28.962 C18.2@9.136,-28.956 C18.2@-15.883,19.044 C18.2@-15.883,-28.962 C18.2@-40.902,19.038 C18.2@-40.902,-28.962 C19.1@8.136,-28.067 C19.1@-16.883,19.933 C19.1@-16.883,-28.073 C19.1@-41.902,19.927 C19.1@-41.902,-28.073 C19.2@9.136,-28.067 C19.2@-15.883,19.933 C19.2@-15.883,-28.073 C19.2@-40.902,19.927 C19.2@-40.902,-28.073 C20.1@8.128,-25.154 C20.1@-16.891,22.846 C20.1@-16.891,-25.16 C20.1@-41.91,22.84 C20.1@-41.91,-25.16 C20.2@8.128,-26.154 C20.2@-16.891,21.846 C20.2@-16.891,-26.16 C20.2@-41.91,21.84 C20.2@-41.91,-26.16 C21.1@10.414,-31.631 C21.1@-14.605,16.369 C21.1@-14.605,-31.637 C21.1@-39.624,16.363 C21.1@-39.624,-31.637 C21.2@10.414,-32.631 C21.2@-14.605,15.369 C21.2@-14.605,-32.637 C21.2@-39.624,15.363 C21.2@-39.624,-32.637 D1.1@21.844,-44.704 D1.1@-3.175,3.296 D1.1@-3.175,-44.71 D1.1@-28.194,3.29 D1.1@-28.194,-44.71 D1.2@21.844,-42.164 D1.2@-3.175,5.836 D1.2@-3.175,-42.17 D1.2@-28.194,5.83 D1.2@-28.194,-42.17 L1.1@16.408,-23.012 L1.1@-8.611,24.988 L1.1@-8.611,-23.018 L1.1@-33.63,24.982 L1.1@-33.63,-23.018 L1.2@16.408,-24.74 L1.2@-8.611,23.26 L1.2@-8.611,-24.746 L1.2@-33.63,23.254 L1.2@-33.63,-24.746 L2.1@12.827,-22.327 L2.1@-12.192,25.673 L2.1@-12.192,-22.333 L2.1@-37.211,25.667 L2.1@-37.211,-22.333 L2.2@12.827,-20.599 L2.2@-12.192,27.401 L2.2@-12.192,-20.605 L2.2@-37.211,27.395 L2.2@-37.211,-20.605 L3.1@11.43,-22.327 L3.1@-13.589,25.673 L3.1@-13.589,-22.333 L3.1@-38.608,25.667 L3.1@-38.608,-22.333 L3.2@11.43,-20.599 L3.2@-13.589,27.401 L3.2@-13.589,-20.605 L3.2@-38.608,27.395 L3.2@-38.608,-20.605 L4.1@9.144,-25.154 L4.1@-15.875,22.846 L4.1@-15.875,-25.16 L4.1@-40.894,22.84 L4.1@-40.894,-25.16 L4.2@9.144,-26.154 L4.2@-15.875,21.846 L4.2@-15.875,-26.16 L4.2@-40.894,21.84 L4.2@-40.894,-26.16 P1.1@13.716,-46.482 P1.1@-11.303,1.518 P1.1@-11.303,-46.488 P1.1@-36.322,1.512 P1.1@-36.322,-46.488 P1.2@11.176,-46.482 P1.2@-13.843,1.518 P1.2@-13.843,-46.488 P1.2@-38.862,1.512 P1.2@-38.862,-46.488 P1.3@8.636,-46.482 P1.3@-16.383,1.518 P1.3@-16.383,-46.488 P1.3@-41.402,1.512 P1.3@-41.402,-46.488 P1.4@6.096,-46.482 P1.4@-18.923,1.518 P1.4@-18.923,-46.488 P1.4@-43.942,1.512 P1.4@-43.942,-46.488 P1.5@3.556,-46.482 P1.5@-21.463,1.518 P1.5@-21.463,-46.488 P1.5@-46.482,1.512 P1.5@-46.482,-46.488 R1.1@5.461,-40.234 R1.1@-19.558,7.766 R1.1@-19.558,-40.24 R1.1@-44.577,7.76 R1.1@-44.577,-40.24 R1.2@5.461,-38.506 R1.2@-19.558,9.494 R1.2@-19.558,-38.512 R1.2@-44.577,9.488 R1.2@-44.577,-38.512 R2.1@12.827,-24.884 R2.1@-12.192,23.116 R2.1@-12.192,-24.89 R2.1@-37.211,23.11 R2.1@-37.211,-24.89 R2.2@12.827,-23.884 R2.2@-12.192,24.116 R2.2@-12.192,-23.89 R2.2@-37.211,24.11 R2.2@-37.211,-23.89 R3.1@17.043,-46.101 R3.1@-7.976,1.899 R3.1@-7.976,-46.107 R3.1@-32.995,1.893 R3.1@-32.995,-46.107 R3.2@18.771,-46.101 R3.2@-6.248,1.899 R3.2@-6.248,-46.107 R3.2@-31.267,1.893 R3.2@-31.267,-46.107 R4.1@8.136,-27.178 R4.1@-16.883,20.822 R4.1@-16.883,-27.184 R4.1@-41.902,20.816 R4.1@-41.902,-27.184 R4.2@9.136,-27.178 R4.2@-15.883,20.822 R4.2@-15.883,-27.184 R4.2@-40.902,20.816 R4.2@-40.902,-27.184 U1.1@18.22,-41.662 U1.1@-6.799,6.338 U1.1@-6.799,-41.668 U1.1@-31.818,6.332 U1.1@-31.818,-41.668 U1.2 U1.3@18.22,-40.062 U1.3@-6.799,7.938 U1.3@-6.799,-40.068 U1.3@-31.818,7.932 U1.3@-31.818,-40.068 U1.4@18.22,-39.262 U1.4@-6.799,8.738 U1.4@-6.799,-39.268 U1.4@-31.818,8.732 U1.4@-31.818,-39.268 U1.5@18.22,-38.462 U1.5@-6.799,9.538 U1.5@-6.799,-38.468 U1.5@-31.818,9.532 U1.5@-31.818,-38.468 U1.6@18.22,-37.662 U1.6@-6.799,10.338 U1.6@-6.799,-37.668 U1.6@-31.818,10.332 U1.6@-31.818,-37.668 U1.7 U1.8 U1.9@16.77,-34.612 U1.9@-8.249,13.388 U1.9@-8.249,-34.618 U1.9@-33.268,13.382 U1.9@-33.268,-34.618 U1.10 U1.11 U1.12@14.37,-34.612 U1.12@-10.649,13.388 U1.12@-10.649,-34.618 U1.12@-35.668,13.382 U1.12@-35.668,-34.618 U1.13@13.57,-34.612 U1.13@-11.449,13.388 U1.13@-11.449,-34.618 U1.13@-36.468,13.382 U1.13@-36.468,-34.618 U1.14@12.77,-34.612 U1.14@-12.249,13.388 U1.14@-12.249,-34.618 U1.14@-37.268,13.382 U1.14@-37.268,-34.618 U1.15@11.97,-34.612 U1.15@-13.049,13.388 U1.15@-13.049,-34.618 U1.15@-38.068,13.382 U1.15@-38.068,-34.618 U1.16@11.17,-34.612 U1.16@-13.849,13.388 U1.16@-13.849,-34.618 U1.16@-38.868,13.382 U1.16@-38.868,-34.618 U1.17@9.72,-36.062 U1.17@-15.299,11.938 U1.17@-15.299,-36.068 U1.17@-40.318,11.932 U1.17@-40.318,-36.068 U1.18 U1.19 U1.20 U1.21@9.72,-39.262 U1.21@-15.299,8.738 U1.21@-15.299,-39.268 U1.21@-40.318,8.732 U1.21@-40.318,-39.268 U1.22 U1.23 U1.24 U1.25 U1.26 U1.27 U1.28 U1.29@14.37,-43.112 U1.29@-10.649,4.888 U1.29@-10.649,-43.118 U1.29@-35.668,4.882 U1.29@-35.668,-43.118 U1.30 U1.31 U1.32@16.77,-43.112 U1.32@-8.249,4.888 U1.32@-8.249,-43.118 U1.32@-33.268,4.882 U1.32@-33.268,-43.118 U2.1@14.991,-27.037 U2.1@-10.028,20.963 U2.1@-10.028,-27.043 U2.1@-35.047,20.957 U2.1@-35.047,-27.043 U2.2@14.491,-27.037 U2.2@-10.528,20.963 U2.2@-10.528,-27.043 U2.2@-35.547,20.957 U2.2@-35.547,-27.043 U2.3@13.991,-27.037 U2.3@-11.028,20.963 U2.3@-11.028,-27.043 U2.3@-36.047,20.957 U2.3@-36.047,-27.043 U2.4@13.491,-27.037 U2.4@-11.528,20.963 U2.4@-11.528,-27.043 U2.4@-36.547,20.957 U2.4@-36.547,-27.043 U2.5@12.991,-27.037 U2.5@-12.028,20.963 U2.5@-12.028,-27.043 U2.5@-37.047,20.957 U2.5@-37.047,-27.043 U2.6@12.491,-27.037 U2.6@-12.528,20.963 U2.6@-12.528,-27.043 U2.6@-37.547,20.957 U2.6@-37.547,-27.043 U2.7@11.771,-27.757 U2.7@-13.248,20.243 U2.7@-13.248,-27.763 U2.7@-38.267,20.237 U2.7@-38.267,-27.763 U2.8@11.771,-28.257 U2.8@-13.248,19.743 U2.8@-13.248,-28.263 U2.8@-38.267,19.737 U2.8@-38.267,-28.263 U2.9@11.771,-28.757 U2.9@-13.248,19.243 U2.9@-13.248,-28.763 U2.9@-38.267,19.237 U2.9@-38.267,-28.763 U2.10@11.771,-29.257 U2.10@-13.248,18.743 U2.10@-13.248,-29.263 U2.10@-38.267,18.737 U2.10@-38.267,-29.263 U2.11@11.771,-29.757 U2.11@-13.248,18.243 U2.11@-13.248,-29.763 U2.11@-38.267,18.237 U2.11@-38.267,-29.763 U2.12@11.771,-30.257 U2.12@-13.248,17.743 U2.12@-13.248,-30.263 U2.12@-38.267,17.737 U2.12@-38.267,-30.263 U2.13@12.491,-30.977 U2.13@-12.528,17.023 U2.13@-12.528,-30.983 U2.13@-37.547,17.017 U2.13@-37.547,-30.983 U2.14@12.991,-30.977 U2.14@-12.028,17.023 U2.14@-12.028,-30.983 U2.14@-37.047,17.017 U2.14@-37.047,-30.983 U2.15@13.491,-30.977 U2.15@-11.528,17.023 U2.15@-11.528,-30.983 U2.15@-36.547,17.017 U2.15@-36.547,-30.983 U2.16@13.991,-30.977 U2.16@-11.028,17.023 U2.16@-11.028,-30.983 U2.16@-36.047,17.017 U2.16@-36.047,-30.983 U2.17@14.491,-30.977 U2.17@-10.528,17.023 U2.17@-10.528,-30.983 U2.17@-35.547,17.017 U2.17@-35.547,-30.983 U2.18@14.991,-30.977 U2.18@-10.028,17.023 U2.18@-10.028,-30.983 U2.18@-35.047,17.017 U2.18@-35.047,-30.983 U2.19@15.711,-30.257 U2.19@-9.308,17.743 U2.19@-9.308,-30.263 U2.19@-34.327,17.737 U2.19@-34.327,-30.263 U2.20@15.711,-29.757 U2.20@-9.308,18.243 U2.20@-9.308,-29.763 U2.20@-34.327,18.237 U2.20@-34.327,-29.763 U2.21 U2.22@15.711,-28.757 U2.22@-9.308,19.243 U2.22@-9.308,-28.763 U2.22@-34.327,19.237 U2.22@-34.327,-28.763 U2.23@15.711,-28.257 U2.23@-9.308,19.743 U2.23@-9.308,-28.263 U2.23@-34.327,19.737 U2.23@-34.327,-28.263 U2.24@15.711,-27.757 U2.24@-9.308,20.243 U2.24@-9.308,-27.763 U2.24@-34.327,20.237 U2.24@-34.327,-27.763 U2.25@13.741,-29.007 U2.25@-11.278,18.993 U2.25@-11.278,-29.013 U2.25@-36.297,18.987 U2.25@-36.297,-29.013 Y1.1@7.417,-30.226 Y1.1@-17.602,17.774 Y1.1@-17.602,-30.232 Y1.1@-42.621,17.768 Y1.1@-42.621,-30.232 Y1.2 Y1.3@9.017,-32.426 Y1.3@-16.002,15.574 Y1.3@-16.002,-32.432 Y1.3@-41.021,15.568 Y1.3@-41.021,-32.432 Y1.4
